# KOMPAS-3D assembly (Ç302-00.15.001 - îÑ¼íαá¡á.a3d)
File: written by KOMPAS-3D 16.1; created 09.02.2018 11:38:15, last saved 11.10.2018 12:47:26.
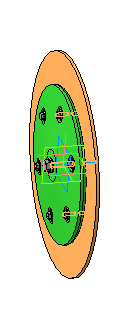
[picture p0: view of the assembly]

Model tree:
1. Массив по образцу:1  (6 pattern instances)
2. Сечение поверхностью:1  (labels: А302-00.15.000; SYSTEM_PROPERTY_ADDITIONAL_FOR:5.000000; ГОСТ Р 55739-2013)
     Расстояние = -0.5; Расстояние = -0.5

Expressions: A2-70; М5 x 30 - A2-70; М8 x 30 - A2-70
Referenced files in Z:\Мембранные насосы\Мембранный электропривод\А302-00.00.000 - ASTRA-302 (МЭ200)\3Д\: А302-00.15.001 - Мембрана.m3d, А302-00.15.003 - Шайба.m3d, А302-00.15.002 - Упор.m3d
Referenced files in C:\Program Files\ASCON\KOMPAS-3D V16\Libs\PartLib\DATA\vault\Methods\Kompas\3D\: PLib_Bolt_1_ISO_1100.m3d
Referenced files in Z:\2 Стандартные изделия 3D\Гайки\DIN 6927\: Гайка шестигранная самостопорящаяся с фланцем DIN 6927-M6 - A2-70.m3d
Referenced files in Z:\1 ПКИ 3D\РТИ\Кольца уплотнительные  плоские\: Кольцо плоское уплотнительное 5-13-10 Ф4.m3d, Кольцо плоское уплотнительное 7-18-10 Ф4.m3d
Referenced files in \\192.168.87.28\Konstructor_doc\Мембранные насосы\Мембранный электропривод\А302-00.00.000 - ASTRA-302 (МЭ200)\Чертежи\: А302-00.15.001 - Мембрана.cdw, А302-00.15.003 - Шайба.cdw, А302-00.15.002 - Упор.cdw
Referenced files: GRAPHIC.TDP
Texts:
  Болт с шестигранной головкой с фланцем ГОСТ Р 55739 - М5 x 30 - A2-70
  hole1
  hole2
  Болт с шестигранной головкой с фланцем
  ГОСТ Р  55739-М5 x 30-A2-70
  Гайка шестигранная самостопорящаяся
  с фланцем DIN 6927-M6-A2-70
  Кольцо плоское уплотнительное
  Кольцо плоское уплотнительное / 05-13-10 Фторопласт
  @2~4,7х@2~13S=1мм
  Болт с шестигранной головкой с фланцем ГОСТ Р 55739 - М8 x 30 - A2-70
  ГОСТ Р  55739-М8 x 30-A2-70
  Кольцо плоское уплотнительное / 07-18-10 Фторопласт
  @2~6,8х@2~18S=1мм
